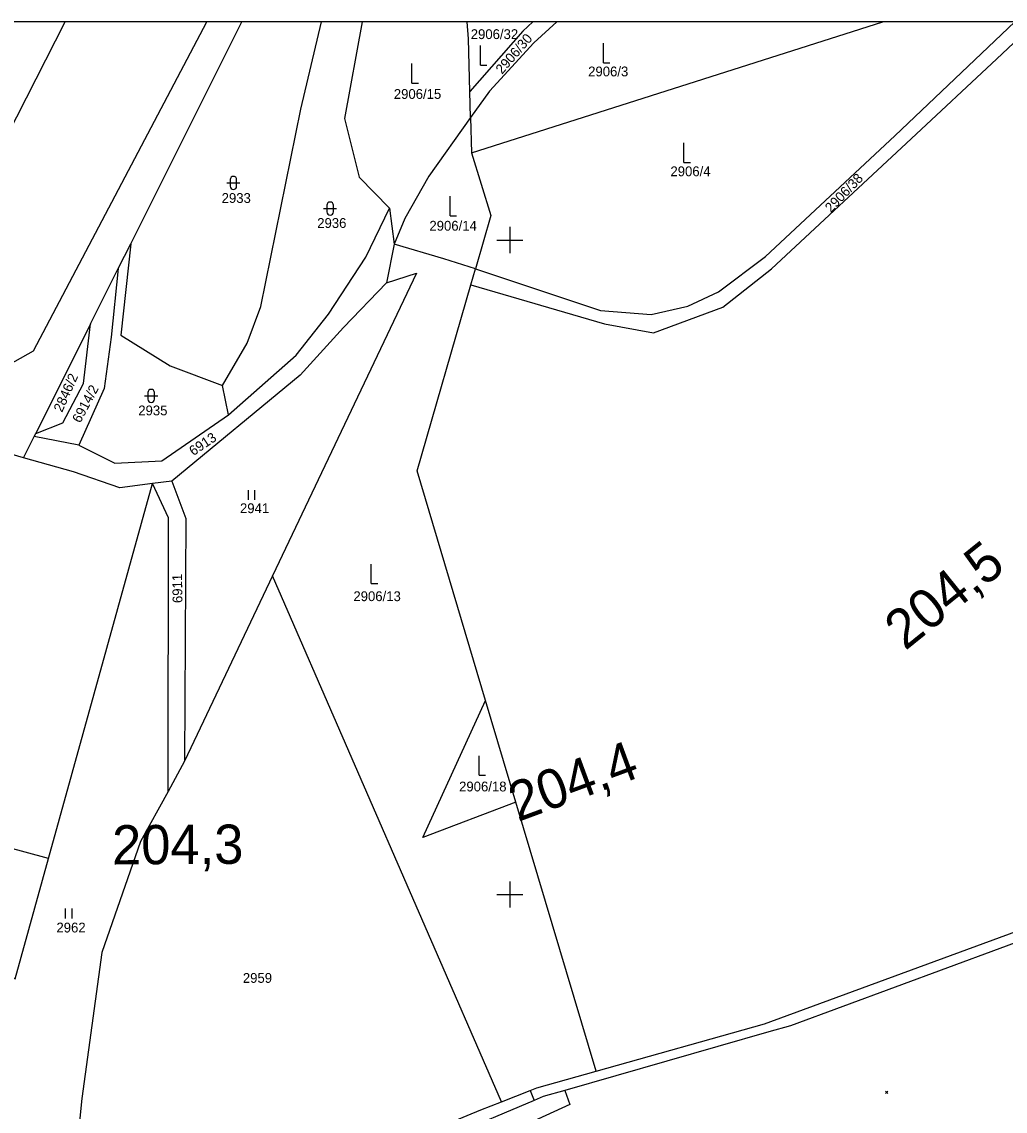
# Model space of a CAD drawing. Extents: x -800194 to -799078, y -1007177 to -1006597.
# Drawn here: x -799674.6 to -799524.3, y -1006933.1 to -1006766.6 of the extents above; entities that cross this region are included whole.
import ezdxf

# ---------------------------------------------------------------- set-up
doc = ezdxf.new("R2010")
doc.units = 0
for name, color, linetype in [('_Vrstva 7 - Přesunutá', 7, 'Continuous'), ('Legenda 1', 7, 'Continuous'), ('Ramove udaje', 7, 'Continuous'), ('Vrstva 49', 7, 'Continuous'), ('Vrstva 55', 7, 'Continuous'), ('Vrstva 57', 7, 'Continuous'), ('Vrstva 58', 7, 'Continuous')]:
    doc.layers.add(name, color=color, linetype=linetype)

msp = doc.modelspace()

# ---------------------------------------------------------------- linework, layer by layer
at = {"layer": 'Legenda 1'}
msp.add_lwpolyline([(-800193.4, -1007176.65), (-799312.4, -1007176.65), (-799312.4, -1006766.65), (-800193.4, -1006766.65)], close=True, dxfattribs=at)
at = {"layer": 'Ramove udaje'}
for p, q in [((-799600, -1006798), (-799600, -1006802)), ((-799602, -1006800), (-799600, -1006800)), ((-799600, -1006800), (-799598, -1006800)), ((-799600, -1006898), (-799600, -1006902)), ((-799602, -1006900), (-799600, -1006900)), ((-799600, -1006900), (-799598, -1006900))]:
    msp.add_line(p, q, dxfattribs=at)
at = {"layer": 'Vrstva 49'}
for p, q in [((-799542.55, -1006930.05), (-799542.2, -1006930.4)), ((-799542.55, -1006930.4), (-799542.2, -1006930.05))]:
    msp.add_line(p, q, dxfattribs=at)
at = {"layer": 'Vrstva 55'}
for p, q in [((-799657.97, -1006800.56), (-799640.98, -1006766.65)), ((-799605.86, -1006786.69), (-799542.97, -1006766.65)), ((-799606.01, -1006781.28), (-799606.12, -1006777.32)), ((-799606.01, -1006781.28), (-799612.39, -1006790.22)), ((-799606.01, -1006781.28), (-799605.86, -1006786.69)), ((-799618.4, -1006795.15), (-799617.67, -1006800.63)), ((-799659.88, -1006804.37), (-799657.97, -1006800.56)), ((-799617.67, -1006800.63), (-799618.84, -1006806.56)), ((-799610.07, -1006802.89), (-799617.67, -1006800.63)), ((-799605.25, -1006804.42), (-799610.07, -1006802.89)), ((-799664.11, -1006812.82), (-799659.88, -1006804.37)), ((-799605.96, -1006806.87), (-799605.25, -1006804.42)), ((-799614.27, -1006805.04), (-799636.28, -1006851.33)), ((-799618.84, -1006806.56), (-799614.27, -1006805.04)), ((-799664.11, -1006812.82), (-799672.49, -1006829.54)), ((-799643, -1006826.73), (-799643.92, -1006822.23)), ((-799672.74, -1006830.04), (-799672.49, -1006829.54)), ((-799674.35, -1006833.26), (-799684.1, -1006830.47)), ((-799674.35, -1006833.26), (-799672.74, -1006830.04)), ((-799665.89, -1006831.36), (-799672.74, -1006830.04)), ((-799670.51, -1006894.51), (-799654.65, -1006837.22)), ((-799651.68, -1006836.84), (-799654.65, -1006837.22)), ((-799636.28, -1006851.33), (-799649.74, -1006879.63)), ((-799601.26, -1006931.67), (-799636.28, -1006851.33)), ((-799599.08, -1006885.89), (-799603.7, -1006870.39)), ((-799649.74, -1006879.63), (-799652.26, -1006884.27)), ((-799586.79, -1006927.02), (-799599.08, -1006885.89)), ((-799601.26, -1006931.67), (-799596.88, -1006929.97)), ((-799596.88, -1006929.97), (-799596.27, -1006931.47)), ((-799594.91, -1006930.9), (-799596.27, -1006931.47)), ((-799591.61, -1006929.95), (-799594.91, -1006930.9)), ((-799668.25, -1006959.17), (-799604.43, -1006932.91)), ((-799596.27, -1006931.47), (-799668.03, -1006961.74)), ((-799604.43, -1006932.91), (-799601.26, -1006931.67))]:
    msp.add_line(p, q, dxfattribs=at)
for points in [[(-799843.37, -1006876), (-799831.92, -1006878.98), (-799822.92, -1006880.05), (-799810.74, -1006879.32), (-799788.82, -1006876.36), (-799777.45, -1006873.96), (-799762.31, -1006868.73), (-799765.35, -1006860.47), (-799748.13, -1006852.13), (-799728.87, -1006839.09), (-799711.19, -1006826.38), (-799689.75, -1006803.29), (-799676.83, -1006784.06), (-799667.97, -1006766.65)], [(-799830.3, -1006886.5), (-799827.05, -1006886.7), (-799816.55, -1006886.06), (-799808.97, -1006887.52), (-799807.07, -1006887.91), (-799799.23, -1006886.45), (-799786.57, -1006884.64), (-799768.13, -1006880.63), (-799748.15, -1006872.9), (-799715.76, -1006852.76), (-799688.4, -1006825.67), (-799672.84, -1006816.93), (-799646.34, -1006766.65)], [(-799643.92, -1006822.23), (-799640.14, -1006815.75), (-799638.06, -1006810.17), (-799631.94, -1006780), (-799628.82, -1006766.65)], [(-799622.6, -1006766.65), (-799625.3, -1006781.44), (-799623.03, -1006790.37), (-799618.4, -1006795.15)], [(-799606.12, -1006777.32), (-799606.33, -1006769.27), (-799606.52, -1006766.65)], [(-799596.5, -1006766.65), (-799598, -1006768.07), (-799606.12, -1006777.32)], [(-799592.83, -1006766.65), (-799596.32, -1006769.88), (-799603.13, -1006777.25), (-799606.01, -1006781.28)], [(-799605.96, -1006806.87), (-799585.51, -1006812.81), (-799578.02, -1006814.17), (-799567.46, -1006810.26), (-799560.01, -1006804.4), (-799538.65, -1006784.55), (-799525.56, -1006772.33), (-799519.54, -1006766.65)], [(-799605.25, -1006804.42), (-799586.13, -1006810.77), (-799578.39, -1006811.38), (-799572.8, -1006810.09), (-799568.08, -1006807.93), (-799560.91, -1006802.54), (-799541.14, -1006784.06), (-799522.78, -1006766.65)], [(-799605.86, -1006786.69), (-799602.89, -1006796.25), (-799605.25, -1006804.42)], [(-799612.39, -1006790.22), (-799616.05, -1006796.73), (-799617.67, -1006800.63)], [(-799643, -1006826.73), (-799632.68, -1006817.6), (-799627.72, -1006811.33), (-799622.02, -1006802.64), (-799618.4, -1006795.15)], [(-799657.97, -1006800.56), (-799659.48, -1006814.54), (-799651.93, -1006819.24), (-799643.92, -1006822.23)], [(-799659.88, -1006804.37), (-799660.95, -1006814.84), (-799662.01, -1006822.68), (-799665.89, -1006831.36)], [(-799618.84, -1006806.56), (-799625.43, -1006813.35), (-799632.06, -1006820.64), (-799651.68, -1006836.84)], [(-799603.7, -1006870.39), (-799614.19, -1006835.28), (-799605.96, -1006806.87)], [(-799672.49, -1006829.54), (-799668.34, -1006827.91), (-799665.16, -1006821.93), (-799664.11, -1006812.82)], [(-799665.89, -1006831.36), (-799660.37, -1006834.11), (-799653.21, -1006833.72), (-799643, -1006826.73)], [(-799654.65, -1006837.22), (-799659.61, -1006837.85), (-799666.73, -1006835.44), (-799674.35, -1006833.26)], [(-799652.26, -1006884.27), (-799652.17, -1006842.45), (-799654.65, -1006837.22)], [(-799651.68, -1006836.84), (-799649.56, -1006842.56), (-799649.74, -1006879.63)], [(-799599.08, -1006885.89), (-799613.33, -1006891.29), (-799603.7, -1006870.39)], [(-799652.26, -1006884.27), (-799656.47, -1006891.91), (-799662.36, -1006908.86), (-799665.44, -1006931.17), (-799668.25, -1006959.17)], [(-799670.51, -1006894.51), (-799686.74, -1006890.11), (-799691.31, -1006907.33)], [(-799679.26, -1006911.01), (-799675.61, -1006912.91), (-799670.51, -1006894.51)], [(-799586.79, -1006927.02), (-799561.07, -1006919.79), (-799500.17, -1006897.39), (-799498.58, -1006896.8)], [(-799506.49, -1006901.85), (-799516.91, -1006905.73), (-799517.11, -1006905.3), (-799557.12, -1006920.07)], [(-799557.12, -1006920.07), (-799560.43, -1006921.02), (-799591.61, -1006929.95)], [(-799596.88, -1006929.97), (-799595.89, -1006929.58), (-799586.79, -1006927.02)], [(-799591.61, -1006929.95), (-799590.84, -1006932.11), (-799616.41, -1006943.81), (-799620.83, -1006945.58), (-799661.1, -1006960.05), (-799668, -1006962.02)]]:
    msp.add_lwpolyline(points, dxfattribs=at)
at = {"layer": 'Vrstva 58'}
for p, q in [((-799604.51, -1006773.29), (-799604.51, -1006770.29)), ((-799585.7, -1006772.93), (-799585.7, -1006769.93)), ((-799614.99, -1006776.01), (-799614.99, -1006773.01)), ((-799585.7, -1006772.93), (-799584.7, -1006772.93)), ((-799604.51, -1006773.29), (-799603.51, -1006773.29)), ((-799614.99, -1006776.01), (-799613.99, -1006776.01)), ((-799573.38, -1006788.16), (-799573.38, -1006785.16)), ((-799573.38, -1006788.16), (-799572.38, -1006788.16)), ((-799643.27, -1006791.27), (-799641.27, -1006791.27)), ((-799642.77, -1006790.77), (-799642.77, -1006791.77)), ((-799641.77, -1006791.77), (-799641.77, -1006790.77)), ((-799627.98, -1006794.69), (-799627.98, -1006795.69)), ((-799626.98, -1006795.69), (-799626.98, -1006794.69)), ((-799609.15, -1006796.29), (-799609.15, -1006793.29)), ((-799628.48, -1006795.19), (-799626.48, -1006795.19)), ((-799609.15, -1006796.29), (-799608.15, -1006796.29)), ((-799655.84, -1006823.82), (-799653.84, -1006823.82)), ((-799655.34, -1006823.32), (-799655.34, -1006824.32)), ((-799654.34, -1006824.32), (-799654.34, -1006823.32)), ((-799639.98, -1006839.71), (-799639.98, -1006838.21)), ((-799638.98, -1006839.71), (-799638.98, -1006838.21)), ((-799621.18, -1006852.51), (-799621.18, -1006849.51)), ((-799621.18, -1006852.51), (-799620.18, -1006852.51)), ((-799604.71, -1006881.8), (-799604.71, -1006878.8)), ((-799604.71, -1006881.8), (-799603.71, -1006881.8)), ((-799667.92, -1006903.67), (-799667.92, -1006902.17)), ((-799666.92, -1006903.67), (-799666.92, -1006902.17))]:
    msp.add_line(p, q, dxfattribs=at)
for centre, start, end in [((-799642.27, -1006790.77), 0, 180), ((-799642.27, -1006791.77), 180, 359.9879), ((-799627.48, -1006794.69), 0, 180), ((-799627.48, -1006795.69), 180, 359.9879), ((-799654.84, -1006823.32), 0, 180), ((-799654.84, -1006824.32), 180, 359.9879)]:
    msp.add_arc(centre, 0.5, start, end, dxfattribs=at)

# ---------------------------------------------------------------- texts
at = {"layer": '_Vrstva 7 - Přesunutá'}
for s, rotation, p in [('204,5', 38.8758, (-799539.57, -1006862.84)), ('204,4', 20.2403, (-799598.78, -1006888.95)), ('204,3', 0.3246, (-799660.8, -1006895.43))]:
    msp.add_text(s, height=6, rotation=rotation, dxfattribs=at).set_placement(p)
at = {"layer": 'Vrstva 57'}
for s, p in [('2906/32', (-799605.98, -1006769.29)), ('2906/3', (-799588.03, -1006774.99)), ('2906/15', (-799617.74, -1006778.43)), ('2906/4', (-799575.45, -1006790.25)), ('2933', (-799644.06, -1006794.33)), ('2936', (-799629.45, -1006798.15)), ('2906/14', (-799612.3, -1006798.57)), ('2935', (-799656.81, -1006826.79)), ('2941', (-799641.26, -1006841.73)), ('2906/13', (-799623.92, -1006855.18)), ('2906/18', (-799607.76, -1006884.26)), ('2962', (-799669.32, -1006905.81)), ('2959', (-799640.82, -1006913.51))]:
    msp.add_text(s, height=1.5, dxfattribs=at).set_placement(p)
for s, rotation, p in [('2906/30', 49.0973, (-799601.19, -1006774.75)), ('2906/38', 46, (-799550.91, -1006795.91)), ('2846/2', 66, (-799668.46, -1006826.42)), ('6914/2', 62, (-799665.68, -1006828.07)), ('6913', 34, (-799648.39, -1006833.03)), ('6911', 91, (-799650.05, -1006855.46))]:
    msp.add_text(s, height=1.5, rotation=rotation, dxfattribs=at).set_placement(p)

doc.saveas('drawing.dxf')
